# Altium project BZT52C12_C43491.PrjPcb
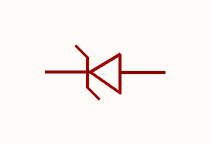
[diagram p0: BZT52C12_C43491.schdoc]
1 sheet, 1 parts. Net scope: global (net labels, ports and power ports of the same name join across sheets).

## Sheet BZT52C12_C43491.schdoc
size 127 x 101 mm

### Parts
ZD?  bzt52c12_c43491  [SOD-123_L2.8-W1.8-LS3.7-RD]  (value not drawn)

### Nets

Not connected (* = marked no-connect by the designer): ZD? 1(K) 2(A)

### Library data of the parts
ZD? = bzt52c12_c43491: 二极管配置:1个独立式;稳压值(标称值):12V;稳压值(范围):11.4V~12.7V;耗散功率(Pd):500mW;; Manufacturer: CJ(江苏长电/长晶); AddInBom: yes; ModelId: 7884390a25fb4c08947731ebfba7e3f8; ModelTransform: 144.8816,62.992,0,0,0,0,0,0,0; Diode Configuration: 1个独立式; Zener Voltage(Nom): 12V; Reverse Leakage Current (Ir): 100nA@8V; Pd - Power Dissipation: 500mW; Impedance(Zzt): 25Ω; Impedance(Zzk): 150Ω; Operating Junction Temperature Range: -55℃~+150℃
